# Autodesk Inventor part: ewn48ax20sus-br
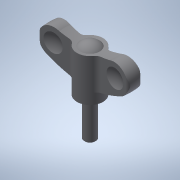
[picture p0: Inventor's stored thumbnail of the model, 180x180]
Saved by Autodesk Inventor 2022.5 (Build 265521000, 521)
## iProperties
Created: 2017-05
Part Number: ewn48ax20sus-br
Material: 一般
Document SubType Name: Modeling
Designer: imaocorp
Density: 1 g/cm^3
Appearance: 既定
Author: imaocorp
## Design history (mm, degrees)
node "ewn48ax20sus-br.x_t1"
node "ewn48ax20sus-br"
node "Base1"
